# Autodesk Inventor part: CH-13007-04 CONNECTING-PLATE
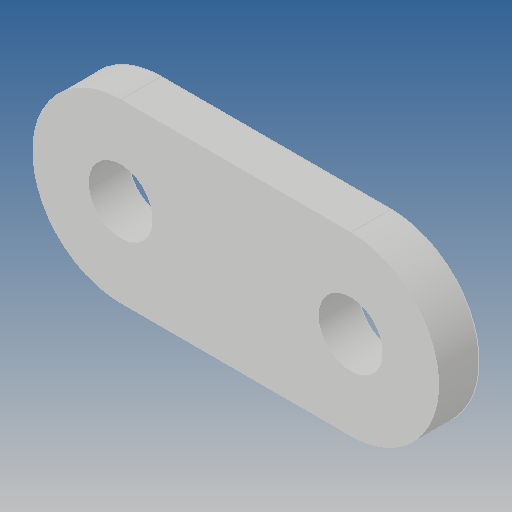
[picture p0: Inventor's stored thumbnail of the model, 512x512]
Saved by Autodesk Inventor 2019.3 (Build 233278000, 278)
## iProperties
Created: 2017-11
Part Number: CH-13007-04 CONNECTING-PLATE
Material: Ogólny
Document SubType Name: Modeling
Designer: Admin
Density: 1 g/cm^3
Appearance: Domyślna
Author: Admin
Revision Number: ÈÎºÎ
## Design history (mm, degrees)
feature "À­Éì1"
node "Bryła1"
